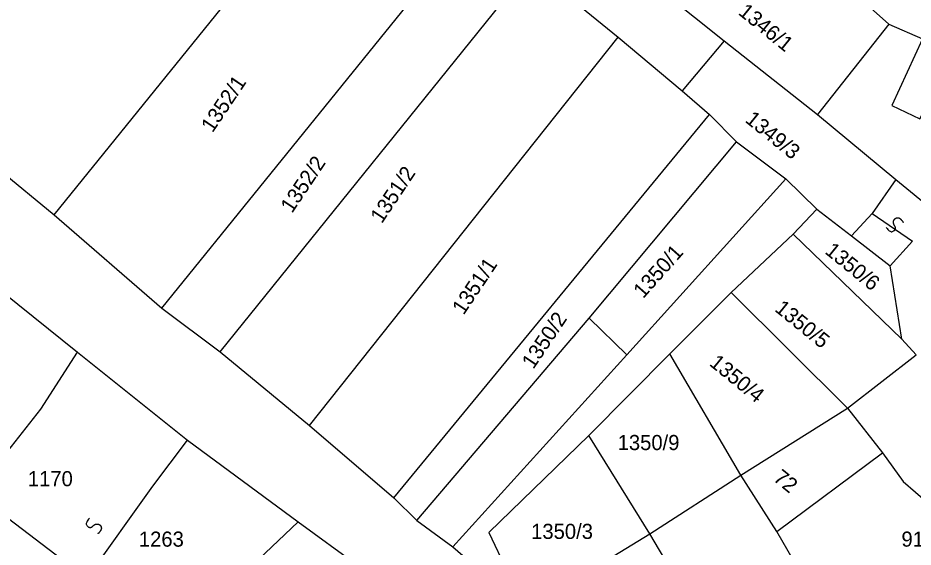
# Model space of a CAD drawing. Extents: x -581999 to -572728, y -1219553 to -1212032.
# Drawn here: x -577931.4 to -577812.9, y -1215555.8 to -1215485.8 of the extents above; entities that cross this region are included whole.
import ezdxf

# ---------------------------------------------------------------- set-up
doc = ezdxf.new("R2010")
doc.units = 0
for name, color, linetype in [('Vrstva 1', 7, 'Continuous'), ('Vrstva 2', 7, 'Continuous'), ('Vrstva 4', 7, 'Continuous'), ('Vrstva 6', 7, 'Continuous')]:
    doc.layers.add(name, color=color, linetype=linetype)

msp = doc.modelspace()

# ---------------------------------------------------------------- linework, layer by layer
at = {"layer": 'Vrstva 1'}
msp.add_line((-577894.295, -1215552.511), (-577886.343, -1215558.33), dxfattribs=at)
for points in [[(-577971.667, -1215390.161), (-577899.516, -1215441.527), (-577893.856, -1215445.25), (-577891.34, -1215447.533), (-577869.986, -1215463.212), (-577837.934, -1215488.834)], [(-577926.587, -1215511.862), (-577886.047, -1215461.736)], [(-577912.354, -1215524.227), (-577871.179, -1215473.356)], [(-577904.637, -1215529.978), (-577863.463, -1215478.938)], [(-577863.463, -1215478.938), (-577851.98, -1215488.347)], [(-577822.237, -1215481.153), (-577816.172, -1215486.628)], [(-577816.172, -1215486.628), (-577825.598, -1215498.591)], [(-577816.172, -1215486.628), (-577811.713, -1215488.553)], [(-577892.807, -1215539.73), (-577851.98, -1215488.347)], [(-577851.98, -1215488.347), (-577843.488, -1215495.465)], [(-577837.934, -1215488.834), (-577843.488, -1215495.465)], [(-577837.934, -1215488.834), (-577825.598, -1215498.591)], [(-577948.48, -1215493.866), (-577926.587, -1215511.862)], [(-577843.488, -1215495.465), (-577839.898, -1215498.569)], [(-577881.667, -1215549.304), (-577839.898, -1215498.569)], [(-577839.898, -1215498.569), (-577836.302, -1215502.224)], [(-577825.598, -1215498.591), (-577815.238, -1215507.197)], [(-577855.786, -1215525.54), (-577836.302, -1215502.224)], [(-577836.302, -1215502.224), (-577829.79, -1215507.103)], [(-577850.82, -1215530.412), (-577829.79, -1215507.103)], [(-577829.79, -1215507.103), (-577825.681, -1215511.105)], [(-577815.238, -1215507.197), (-577818.344, -1215511.69)], [(-577815.238, -1215507.197), (-577810.1, -1215511.377)], [(-577926.587, -1215511.862), (-577912.354, -1215524.227)], [(-577825.681, -1215511.105), (-577828.8, -1215514.409)], [(-577825.681, -1215511.105), (-577821.101, -1215514.624)], [(-577818.344, -1215511.69), (-577821.101, -1215514.624)], [(-577828.8, -1215514.409), (-577837.022, -1215522.143)], [(-577814.449, -1215528.338), (-577828.8, -1215514.409)], [(-577821.101, -1215514.624), (-577815.963, -1215518.63)], [(-577937.307, -1215518.977), (-577923.511, -1215530.033)], [(-577814.449, -1215528.338), (-577815.963, -1215518.63)], [(-577837.022, -1215522.143), (-577845.121, -1215530.254)], [(-577837.022, -1215522.143), (-577821.616, -1215537.451)], [(-577912.354, -1215524.227), (-577904.637, -1215529.978)], [(-577878.625, -1215552.312), (-577855.786, -1215525.54)], [(-577855.786, -1215525.54), (-577850.82, -1215530.412)], [(-577812.539, -1215530.415), (-577814.449, -1215528.338)], [(-577928.334, -1215537.593), (-577923.511, -1215530.033)], [(-577923.511, -1215530.033), (-577908.941, -1215541.693)], [(-577904.637, -1215529.978), (-577892.807, -1215539.73)], [(-577873.825, -1215555.796), (-577850.82, -1215530.412)], [(-577845.121, -1215530.254), (-577855.829, -1215541.052)], [(-577835.751, -1215546.327), (-577845.121, -1215530.254)], [(-577821.616, -1215537.451), (-577812.539, -1215530.415)], [(-577937.129, -1215548.715), (-577928.334, -1215537.593)], [(-577835.751, -1215546.327), (-577821.616, -1215537.451)], [(-577821.616, -1215537.451), (-577816.999, -1215543.359)], [(-577892.807, -1215539.73), (-577881.667, -1215549.304)], [(-577855.829, -1215541.052), (-577869.1, -1215553.904), (-577864.232, -1215564.147)], [(-577847.797, -1215554.076), (-577855.829, -1215541.052)], [(-577913.545, -1215547.79), (-577908.941, -1215541.693)], [(-577908.941, -1215541.693), (-577894.295, -1215552.511), (-577903.903, -1215561.618)], [(-577830.967, -1215553.795), (-577816.999, -1215543.359)], [(-577816.999, -1215543.359), (-577814.264, -1215547.18)], [(-577847.797, -1215554.076), (-577835.751, -1215546.327)], [(-577830.967, -1215553.795), (-577835.751, -1215546.327)], [(-577814.264, -1215547.18), (-577811.012, -1215549.964)], [(-577922.231, -1215559.966), (-577913.545, -1215547.79)], [(-577924.646, -1215558.193), (-577937.129, -1215548.715)], [(-577881.667, -1215549.304), (-577878.625, -1215552.312)], [(-577878.625, -1215552.312), (-577873.825, -1215555.796)], [(-577864.232, -1215564.147), (-577847.797, -1215554.076)], [(-577839.257, -1215568.485), (-577847.797, -1215554.076)], [(-577826.186, -1215562.126), (-577830.967, -1215553.795)], [(-577873.825, -1215555.796), (-577864.232, -1215564.147)]]:
    msp.add_lwpolyline(points, dxfattribs=at)
at = {"layer": 'Vrstva 4'}
for points in [[(-577811.713, -1215488.553), (-577815.773, -1215497.404), (-577812.052, -1215499.154), (-577808.116, -1215491.341)], [(-577818.344, -1215511.69), (-577813.033, -1215515.35)], [(-577815.963, -1215518.63), (-577813.033, -1215515.35)]]:
    msp.add_lwpolyline(points, dxfattribs=at)
at = {"layer": 'Vrstva 6'}
for points in [[(-577816.503, -1215513.521), (-577816.023, -1215514.228), (-577815.329, -1215513.917), (-577815.252, -1215513.517), (-577815.488, -1215513.172), (-577815.573, -1215512.84), (-577815.491, -1215512.55), (-577815.347, -1215512.37), (-577815.111, -1215512.242), (-577814.746, -1215512.278), (-577814.319, -1215512.717), (-577814.264, -1215512.89)], [(-577921.92, -1215552.025), (-577922.507, -1215552.647), (-577922.052, -1215553.256), (-577921.646, -1215553.244), (-577921.36, -1215552.939), (-577921.054, -1215552.785), (-577920.754, -1215552.801), (-577920.547, -1215552.903), (-577920.371, -1215553.106), (-577920.326, -1215553.47), (-577920.661, -1215553.982), (-577920.819, -1215554.074)]]:
    msp.add_open_spline(points, degree=2, dxfattribs=at)

# ---------------------------------------------------------------- texts
at = {"layer": 'Vrstva 2'}
for s, rotation, p in [('1346/1', 320.93288, (-577836.199, -1215485.253)), ('1352/1', 56.1791, (-577905.639, -1215501.096)), ('1349/3', 320.93288, (-577835.293, -1215499.491)), ('1352/2', 56.1791, (-577895.122, -1215511.747)), ('1351/2', 56.1791, (-577883.242, -1215513.111)), ('1350/1', 48.37606, (-577848.663, -1215523.036)), ('1350/6', 320.93288, (-577824.741, -1215516.883)), ('1351/1', 56.1791, (-577872.417, -1215525.211)), ('1350/5', 320.93288, (-577831.382, -1215524.51)), ('1350/2', 56.1791, (-577863.198, -1215532.394)), ('1350/4', 320.93288, (-577840.024, -1215531.709)), ('72', 320.93288, (-577831.579, -1215546.939))]:
    msp.add_text(s, height=2, rotation=rotation, dxfattribs=at).set_placement(p)
for s, p in [('1350/9', (-577852.039, -1215543.002)), ('1170', (-577930.072, -1215547.786)), ('1350/3', (-577863.486, -1215554.761)), ('1263', (-577915.383, -1215555.785)), ('914', (-577814.49, -1215555.784))]:
    msp.add_text(s, height=2, dxfattribs=at).set_placement(p)

doc.saveas('drawing.dxf')
